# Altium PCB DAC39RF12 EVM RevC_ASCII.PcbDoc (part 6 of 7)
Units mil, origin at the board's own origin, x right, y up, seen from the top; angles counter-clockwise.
Board outline 5071.81 x 2716.54 mil, 16 copper layers (Top Layer, L2 GND1, L3 PWR1, L4 GND2, L5 PWR2, L6 GND3, L7 Ctrl Signal 1, L8 GND4, L9 GND5, L10 Ctrl Signal 2, L11 GND6, L12 PWR3, L13 GND7, L14 PWR4, L15 GND8, Bottom Layer), stack 82.4 mil thick; 596 components, 375 nets, 3310 pads, 1662 vias.
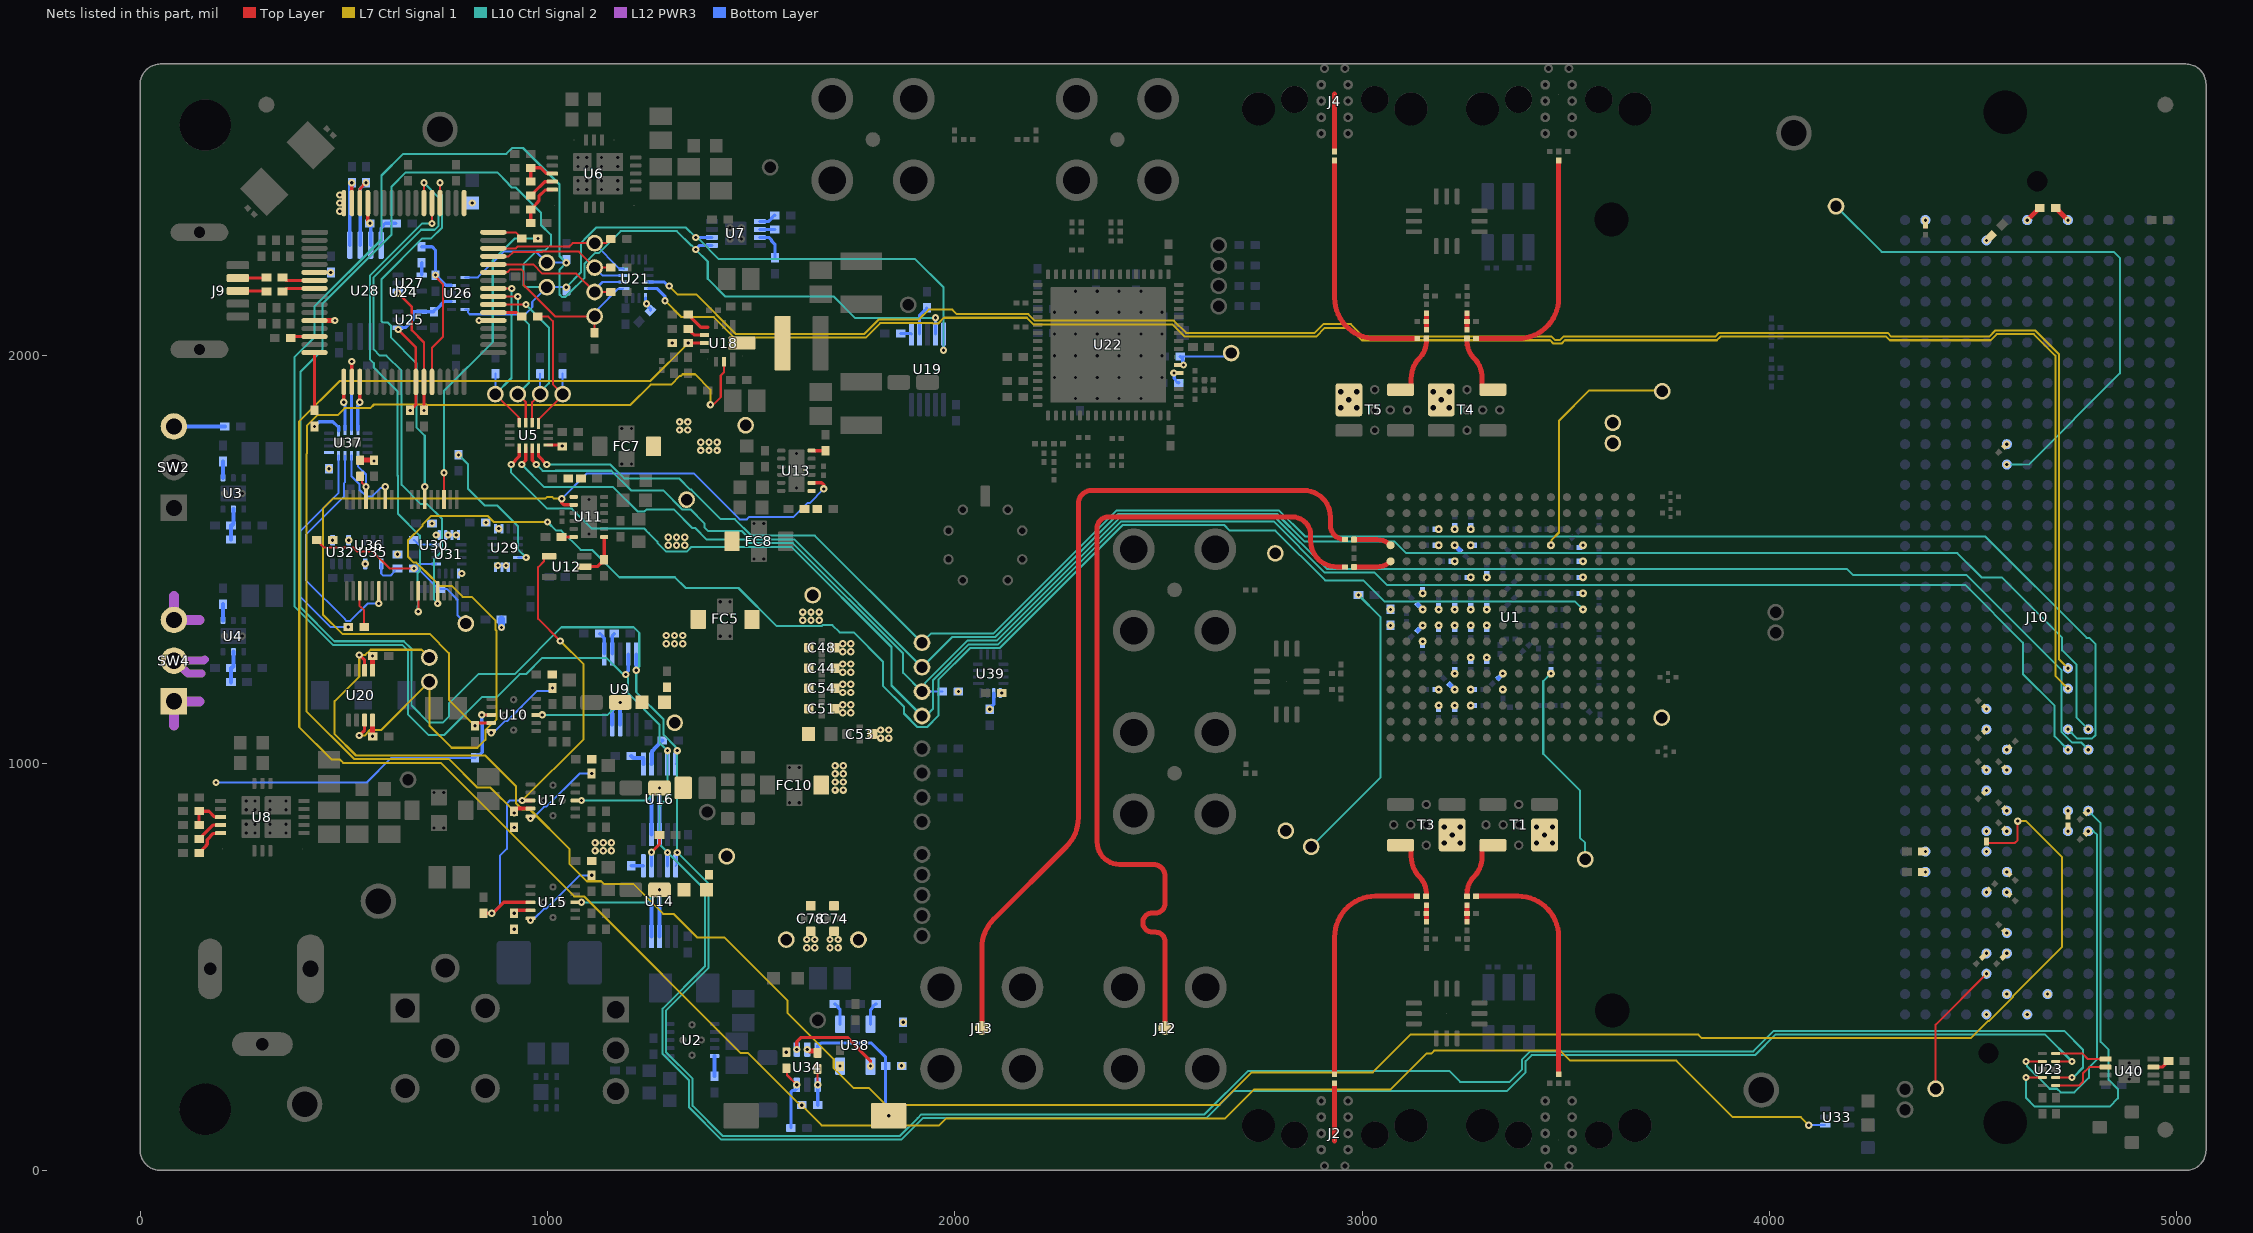
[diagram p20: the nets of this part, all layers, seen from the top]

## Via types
v1: diameter 18, hole 8, Top Layer to Bottom Layer, tented both sides, 1558 vias
v2: diameter 20, hole 10, Top Layer to Bottom Layer, tented both sides, 92 vias
v3: diameter 27, hole 15, Top Layer to Bottom Layer, tented both sides, 12 vias

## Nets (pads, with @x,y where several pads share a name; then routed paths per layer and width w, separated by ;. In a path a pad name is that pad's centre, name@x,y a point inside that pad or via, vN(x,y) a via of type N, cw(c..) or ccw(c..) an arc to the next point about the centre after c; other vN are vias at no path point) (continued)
NetFB3_1: FB3.1 R54.2 U9.8 U9.9 U10.8 | length 336.6
  Top Layer w5: U10.8@972.11,1118.46 v1(987.11,1118.46)
  L10 Ctrl Signal 2 w5: v1(987.11,1118.46) 1147.87,1118.46 v1(1178.58,1149.17)
  Bottom Layer w10: U9.9@1158.89,1094.56 1158.89,1129.49 v1(1178.58,1149.17) U9.8@1178.58,1094.56
NetFB5_1: FB5.1 R71.2 U14.8 U14.9 U15.8 | length 456.6
  Top Layer w5: U15.8@1068.61,658.46 v1(1083.61,658.46)
  L10 Ctrl Signal 2 w5: v1(1083.61,658.46) 1244.33,658.46 v1(1275.08,689.21)
  Bottom Layer w10: U14.9@1255.39,574.59 1255.39,669.52 v1(1275.08,689.21) U14.8@1275.08,574.59
NetFB6_1: FB6.1 R79.2 U16.8 U16.9 U17.8 | length 456.6
  Top Layer w5: U17.8@1068.61,908.46 v1(1083.61,908.46)
  L10 Ctrl Signal 2 w5: v1(1083.61,908.46) 1244.33,908.46 v1(1275.08,939.21)
  Bottom Layer w10: U16.9@1255.39,824.59 1255.39,919.52 v1(1275.08,939.21) U16.8@1275.08,824.59
NetJ2_1: "J2. "@2932.6,75 R10.2 | length 141.4
  Top Layer w12.3: 2932.6,72.62 R10.2@2932.6,214.04
NetJ4_1: "J4. "@2932.6,2641.53 R20.2 | length 141.4
  Top Layer w12.3: R20.2@2932.6,2501.53 2932.6,2642.95
NetJ9_2: J9.2 R124.1 | length 58.5
  Top Layer w8: J9.2@250.16,2190.91 R124.1@308.66,2190.91
NetJ9_3: J9.3 R125.1 | length 58.5
  Top Layer w8: J9.3@250.16,2159.42 R125.1@308.66,2159.42
NetJ10_G12: J10.G12 R156.2
  other v1: 4582.81,1783.06
NetJ10_G13: J10.G13 PP50.1 | length 1402.5
  L10 Ctrl Signal 2 w5: PP50.1@4163.4,2367.25 4275.39,2255.26 4845.07,2255.26 4860,2240.32 4860,1956.94 4636.12,1733.06 v1(4582.81,1733.06)
NetJ10_G27: J10.G27 R161.2
  other v1: 4582.81,1033.06
NetJ10_G28: J10.G28 R163.2
  other v1: 4582.81,983.06
NetJ10_G30: J10.G30 R165.2
  other v1: 4582.81,883.06
NetJ10_G31: J10.G31 R167.2
  other v1: 4582.81,833.06
NetJ10_G33: J10.G33 R169.2
  other v1: 4582.81,733.06
NetJ10_G34: J10.G34 R171.2
  other v1: 4582.81,683.06
NetJ10_G36: J10.G36 R176.2
  other v1: 4582.81,583.06
NetJ10_G37: J10.G37 R177.2 | length 13.3
  Top Layer w8: R177.2@4573.4,523.65 v1(4582.81,533.06)
NetJ10_H25: J10.H25 R158.2
  other v1: 4532.81,1133.06
NetJ10_H26: J10.H26 R159.2
  other v1: 4532.81,1083.06
NetJ10_H28: J10.H28 R160.2
  other v1: 4532.81,983.06
NetJ10_H29: J10.H29 R162.2
  other v1: 4532.81,933.06
NetJ10_H31: J10.H31 R164.2
  other v1: 4532.81,833.06
NetJ10_H32: J10.H32 R166.2
  other v1: 4532.81,783.06
NetJ10_H34: J10.H34 R168.2
  other v1: 4532.83,683.06
NetJ10_H37: J10.H37 R172.2 | length 13.3
  Top Layer w8: R172.2@4523.4,523.65 v1(4532.81,533.06)
NetJ10_H38: J10.H38 PP51.1 | length 334.2
  Top Layer w5: PP51.1@4407.81,200.66 4407.81,358.06 v1(4532.81,483.06)
NetJ10_L1: J10.L1 R178.2 | length 14
  Top Layer w12: R178.2@4382.81,2319.08 v1(4382.81,2333.06)
NetJ10_L32: J10.L32 R179.2
  other v1: 4382.81,783.06
NetJ10_L33: J10.L33 R180.2
  other v1: 4382.81,733.06
NetJ12_1: J12.1 R108.2 | length 2127.1
  Top Layer w12.3: J12.1@2516.35,349.76 2516.35,555.3 2516.35,561.45 ccw(c2492.7,561.45) 2492.7,585.1 2485.07,585.1 cw(c2485.07,608.75) 2485.07,632.4 2492.7,632.4 ccw(c2492.7,656.05) 2516.35,656.05 2516.35,696.3 2516.35,721.78 ccw(c2486.34,721.78) 2486.34,751.79 2404.02,751.79 cw(c2404.02,806.3) 2349.51,806.3 2349.51,1479.83 2349.28,1479.83 2349.28,1576.49 cw(c2377.16,1576.49) 2377.16,1604.37 2828.97,1604.37 cw(c2828.97,1559.51) 2873.83,1559.51 2873.83,1545.65 ccw(c2937.76,1545.65) 2937.76,1481.72 R108.2@2957.76,1481.72
NetJ13_1: J13.1 R110.2 | length 2127.1
  Top Layer w12.3: J13.1@2066.35,349.76 2066.35,546.23 cw(c2166.35,546.23) 2095.64,616.94 2274.13,795.43 ccw(c2203.41,866.14) 2303.41,866.14 2303.41,1637.23 cw(c2335.55,1637.23) 2335.55,1669.36 2857.21,1669.36 cw(c2857.21,1604.42) 2922.16,1604.42 2922.16,1584.42 ccw(c2957.76,1584.42) R110.2@2957.76,1548.82
NetL1_1: L1.1 U18.10
NetPP18_1: PP18.1 R113.2 U22.6 | length 152.4
  Bottom Layer w5: R113.2@2553.54,1998.26 2553.76,1998.26 2660.16,1998.26 2668.72,2006.82 PP18.1@2678.46,2006.82
  Bottom Layer w8: R113.2@2553.76,1998.26 2559.6,1992.42 2559.6,1979.45 v1(2561.51,1977.54)
NetPP32_1: PP32.1 R27.1 R136.1 R141.1 U31.9 | length 537.3
  Top Layer w5: R136.1@433.2,1547.44 435.16,1547.44 442.51,1540.09 442.51,1538.12 451.73,1528.9 485.07,1528.9 485.83,1529.67 523.26,1529.67 533.64,1519.29 571.07,1519.29 612.57,1477.79 v1(672.29,1477.79)
  Bottom Layer w5: PP32.1@800.55,1341.82 PP32.1@799.59,1342.79 778.75,1363.62 778.75,1401.71 752.77,1427.7 736.79,1427.7 R27.1@736.39,1428.1 729.05,1435.44 724.4,1435.44 687.69,1472.15 677.93,1472.15 v1(672.29,1477.79) 673.28,1477.79 679.12,1483.63 679.12,1484.48 683.8,1489.17 U31.9@725.44,1489.17 ; U31.9@725.44,1489.17 U31.9@726.59,1489.17 U31.9@725.44,1489.17
NetPP41_1: PP41.1 R148.2 U1.E6 | length 516.6
  L10 Ctrl Signal 2 w5: v1(3463.51,1219.99) 3444.61,1201.09 3444.61,1023.09 3534.6,933.1 3534.6,817.15 3547.64,804.11 PP41.1@3547.64,762.6
  Bottom Layer w5: v1(3463.51,1219.99) R148.2@3463.51,1228.65
NetPP42_1: PP42.1 U1.N6 | length 599.7
  L7 Ctrl Signal 1 w5: v1(3463.51,1534.95) 3464.43,1535.88 3464.43,1547.36 3483.28,1566.2 3483.28,1840.61 3558.03,1915.36 3734.53,1915.36 cw(c3734.53,1913.06) PP42.1@3736.83,1913.06
NetPP43_1: PP43.1 R149.2 | length 711
  L10 Ctrl Signal 2 w5: PP43.1@2874.85,794.47 3044.81,964.43 3044.81,1359.05 v1(2991.07,1412.79)
NetPP54_1: PP54.1 R138.2 U21.1 U24.43 | length 462.3
  Top Layer w5: U24.43@867.13,2204.69 867.98,2205.54 901.82,2205.54 907.63,2211.35 936.64,2211.35 941.46,2206.53 941.46,2173.86 1018.6,2096.71 PP54.1@1115.72,2096.71 R138.2@1115.72,2056.71
  Bottom Layer w5: PP54.1@1115.72,2096.71 1115.72,2106.45 1125.52,2116.25 1125.52,2116.51 1173.02,2164.02 1184.28,2164.02 U21.1@1185.72,2165.46
NetPP55_1: PP55.1 R139.2 U21.2 U24.44 | length 394.7
  Top Layer w5: U24.44@867.13,2224.38 964.76,2224.38 987.55,2201.58 1070.85,2201.58 PP55.1@1115.72,2156.71 R139.2@1155.72,2156.71
  Bottom Layer w5: PP55.1@1115.72,2161.71 1135.21,2181.2 U21.2@1185.72,2181.2
NetPP56_1: PP56.1 R157.2 U21.3 U24.45 | length 387.6
  Top Layer w5: U24.45@867.13,2244.06 904.9,2244.06 915.58,2254.75 986.72,2254.75 987.55,2255.58 1076.85,2255.58 PP56.1@1115.72,2216.71 R157.2@1155.72,2216.71
  Bottom Layer w5: PP56.1@1115.72,2216.71 1135.48,2196.95 U21.3@1185.72,2196.95
NetPP57_1: PP57.1 R170.2 U21.4 U24.46 | length 397.8
  Top Layer w5: U24.46@867.13,2263.75 922.29,2263.75 926.47,2267.93 1052.82,2267.93 1061.6,2276.71 PP57.1@1115.72,2276.71 1143.75,2276.71 1153.75,2286.71 R170.2@1155.72,2286.71
  Bottom Layer w5: PP57.1@1115.72,2276.71 1115.72,2274.68 1176.26,2214.14 1186.25,2214.14 U21.4@1187.68,2212.7
NetR1_1: R1.1 R3.1 T1.2 | length 159
  Top Layer w12.3: R1.1@3257.61,673.35 3257.61,681.37 cw(c3312.26,681.37) 3273.62,720.02 ccw(c3222.3,771.34) 3294.87,771.34 3294.87,795.39 cw(c3302.6,787.66) 3302.6,798.59 T1.2@3320.99,798.59
NetR1_2: R1.2 R2.2 | length 597.3
  Top Layer w12.3: R1.2@3279.66,673.35 3382.6,673.35 cw(c3382.6,573.35) 3482.6,573.35 3482.6,273.57 R2.2@3482.6,236.09
NetR3_2: R3.2 R4.1 R8.2 | length 40.4
  Top Layer w12.3: R4.1@3257.61,610.9 R8.2@3257.61,631.1 R3.2@3257.61,651.3
NetR5_1: R5.1 R9.1 T3.2 | length 159
  Top Layer w12.3: T3.2@3094.22,798.59 3112.61,798.59 cw(c3112.61,787.66) 3120.33,795.39 3120.33,771.34 ccw(c3192.91,771.34) 3141.59,720.02 cw(c3102.94,681.37) 3157.6,681.37 R5.1@3157.6,673.35
NetR5_2: R5.2 R6.1 R7.2 | length 40.4
  Top Layer w12.3: R6.1@3157.6,610.9 R7.2@3157.6,631.1 R5.2@3157.6,651.3
NetR9_2: R9.2 R10.1 | length 596.5
  Top Layer w12.3: R10.1@2932.6,236.09 2932.6,573.35 cw(c3032.6,573.35) 3032.6,673.35 R9.2@3134.76,673.35
NetR11_1: R11.1 R13.1 T4.2 | length 159
  Top Layer w12.3: R11.1@3257.61,2042.22 3257.61,2034.2 ccw(c3312.27,2034.2) 3273.62,1995.56 cw(c3222.3,1944.24) 3294.87,1944.24 3294.87,1920.19 ccw(c3302.6,1927.91) 3302.6,1916.99 T4.2@3320.99,1916.99
NetR11_2: R11.2 R12.2 | length 597.3
  Top Layer w12.3: R11.2@3279.66,2042.22 3382.6,2042.22 ccw(c3382.6,2142.22) 3482.6,2142.22 3482.6,2442.01 R12.2@3482.6,2479.49
NetR13_2: R13.2 R14.1 R18.2 | length 40.4
  Top Layer w12.3: R13.2@3257.61,2064.27 R18.2@3257.61,2084.47 R14.1@3257.61,2104.67
NetR15_1: R15.1 R19.1 T5.2 | length 159
  Top Layer w12.3: T5.2@3094.22,1916.99 3112.61,1916.99 ccw(c3112.61,1927.91) 3120.33,1920.19 3120.33,1944.24 cw(c3192.91,1944.24) 3141.59,1995.56 ccw(c3102.94,2034.2) 3157.6,2034.2 R15.1@3157.6,2042.22
NetR15_2: R15.2 R16.1 R17.2 | length 40.4
  Top Layer w12.3: R15.2@3157.6,2064.27 R17.2@3157.6,2084.47 R16.1@3157.6,2104.67
NetR19_2: R19.2 R20.1 | length 597.3
  Top Layer w12.3: R20.1@2932.73,2479.49 2932.73,2442.01 2932.73,2142.22 ccw(c3032.73,2142.22) 3032.73,2042.22 R19.2@3135.68,2042.22
NetR22_2: R22.2 U2.10 | length 50
  Bottom Layer w9: R22.2@1410.24,230.95 U2.10@1410.24,280.95
NetR28_1: R28.1 U3.4 | length 40
  Bottom Layer w10: U3.4@203.38,1700.42 R28.1@203.38,1740.42
NetR29_1: R29.1 R32.2 U3.2 | length 78.4
  Bottom Layer w10: R29.1@223.06,1548.65 R32.2@223.06,1583.65 ccw(c223.06,1589.56) 228.97,1589.56 U3.2@228.97,1623.65
NetR30_1: R30.1 U4.4 | length 40
  Bottom Layer w10: U4.4@203.38,1350.42 R30.1@203.38,1390.42
NetR31_1: R31.1 R33.2 U4.2 | length 78.4
  Bottom Layer w10: R31.1@223.06,1198.65 R33.2@223.06,1233.65 ccw(c223.06,1239.56) 228.97,1239.56 U4.2@228.97,1273.65
NetR36_1: R36.1 R40.2 U6.24 | length 115.2
  Top Layer w8: R40.2@959.13,2325.63 R36.1@959.13,2359.63 961.09,2359.63 966.94,2365.47 966.94,2367.44 976.59,2377.1 976.59,2378.13 978.94,2380.47 978.94,2391.79 994.26,2407.11 1011.1,2407.11 U6.24@1011.94,2407.95
NetR39_1: R39.1 R42.2 U6.22 | length 92.7
  Top Layer w8: R42.2@959.13,2427.63 R39.1@959.13,2461.63 983.45,2461.63 996.83,2448.24 1011.02,2448.24 U6.22@1011.94,2447.32
NetR41_2: R41.2 U6.23 | length 68.1
  Top Layer w8: R41.2@959.13,2393.63 961.09,2393.63 966.94,2399.47 966.94,2401.44 993.13,2427.64 U6.23@1011.94,2427.64
NetR44_1: R44.1 U24.38 | length 74.1
  Top Layer w8: U24.38@867.13,2106.27 925.16,2106.27 935.16,2096.27 R44.1@937.13,2096.27
NetR45_1: R45.1 U7.3 | length 100.2
  Bottom Layer w8: R45.1@1558.34,2240.58 1558.34,2273.61 1550.53,2281.42 1550.53,2283.39 1543.34,2290.58 ; 1543.34,2290.58 U7.3@1521.34,2290.58 1543.34,2290.58
NetR47_1: R47.1 U8.24 | length 81.2
  Top Layer w8: R47.1@144.77,779.98 146.74,779.98 152.58,785.83 152.58,787.79 162.24,797.45 162.24,798.48 164.58,800.83 164.58,812.14 179.91,827.47 196.74,827.47 U8.24@197.58,828.31
NetR48_1: R48.1 R50.2 U8.22 | length 92.7
  Top Layer w8: R50.2@144.77,847.98 R48.1@144.77,881.98 169.09,881.98 182.48,868.6 196.66,868.6 U8.22@197.58,867.68
NetR49_2: R49.2 U8.23 | length 68.1
  Top Layer w8: R49.2@144.77,813.98 146.74,813.98 152.58,819.83 152.58,821.79 178.78,847.99 U8.23@197.58,847.99
NetR51_2: R51.2 U9.2 | length 52.2
  Bottom Layer w8: U9.2@1158.89,1267.79 1158.89,1312.4 R51.2@1164.28,1317.79
NetR52_2: R52.2 U9.1 | length 55.7
  Bottom Layer w8: R52.2@1128.3,1317.79 1130.27,1317.79 1136.11,1311.94 1136.11,1309.98 1139.21,1306.88 U9.1@1139.21,1267.79
NetR55_1: R55.1 R57.2 U10.5 | length 195.9
  Bottom Layer w5: v1(861.87,1074.37) 865.39,1074.37 869.61,1078.59 870.99,1078.59 895.43,1103.03 900.74,1103.03 975.24,1177.52 1002.68,1177.52 1009.76,1184.61 v1(1012.11,1184.61)
NetR58_1: R58.1 U11.1 U12.2 | length 112.7
  Top Layer w8: U12.2@1090.56,1482.6 1122.15,1482.6 1131.53,1491.98 1133.5,1491.98 1139.34,1497.82 R58.1@1139.34,1499.79 U11.1@1139.34,1555.42
NetR59_1: R59.1 R61.2 U11.7
NetR60_2: R60.2 U11.12 | length 30
  Top Layer w8: R60.2@1034.54,1555.42 U11.12@1064.54,1555.42
NetR62_1: R62.1 U27.4 | length 30
  Bottom Layer w8: U27.4@691.13,2198.25 R62.1@691.13,2228.25
NetR63_2: R63.2 U7.1 | length 66.4
  Bottom Layer w8: R63.2@1558.34,2344.95 1556.37,2344.95 1550.53,2339.11 1550.53,2337.14 1543.34,2329.95 ; 1543.34,2329.95 U7.1@1521.34,2329.95 1543.34,2329.95
NetR64_1: R64.1 R66.2 U13.7
NetR65_2: R65.2 U13.12 | length 34
  Top Layer w8: U13.12@1648.76,1767.02 R65.2@1682.76,1767.02
NetR67_2: R67.2 U14.2 | length 84.4
  Top Layer w8: v1@1255.47,781.29 v1(1255.39,781.37) 1275.08,801.05 R67.2@1275.08,823.96
  Bottom Layer w8: U14.2@1255.39,747.82 v1(1255.39,781.37)
NetR68_2: R68.2 U14.1 | length 30
  Bottom Layer w8: R68.2@1205.71,747.82 U14.1@1235.71,747.82
NetR72_1: R72.1 R74.2 U15.5 | length 195.9
  Bottom Layer w5: v1(958.37,614.37) 961.89,614.37 966.11,618.59 967.49,618.59 991.93,643.03 997.24,643.03 1078.82,724.61 v1(1108.61,724.61)
NetR75_2: R75.2 U16.2 | length 69.5
  Bottom Layer w10: U16.2@1255.39,997.82 1256.3,998.73 1256.3,1029.16 1266.79,1039.65 1266.79,1040.03 1275.14,1048.38 1275.14,1050.35 1279.98,1055.19 R75.2@1281.95,1055.19
NetR76_2: R76.2 U16.1 | length 46.6
  Bottom Layer w10: R76.2@1205.71,1017.82 1210.55,1012.98 1220.55,1012.98 1220.66,1012.87 1234.8,1012.87 1235.71,1011.97 U16.1@1235.71,997.82
NetR78_2: R78.2 U7.2 | length 37
  Bottom Layer w8: U7.2@1521.34,2310.27 R78.2@1558.34,2310.27
NetR80_1: R80.1 R82.2 U17.5 | length 195.9
  Bottom Layer w5: v1(958.37,864.37) 961.89,864.37 966.11,868.59 967.49,868.59 991.93,893.03 997.24,893.03 1078.82,974.61 v1(1108.61,974.61)
NetR85_2: R85.2 U19.2 | length 72.7
  Bottom Layer w8: U19.2@1913.39,2053.41 1913.39,2099.79 1923.39,2109.8 1925.36,2109.8 1931.2,2115.64 R85.2@1931.2,2117.61
NetR86_2: R86.2 U19.1 | length 27
  Bottom Layer w8: R86.2@1867.19,2054.58 1892.53,2054.58 U19.1@1893.7,2053.41
NetR88_2: R88.2 U18.2 | length 47.5
  Top Layer w8: R88.2@1345.62,2066.18 1347.59,2066.18 1353.43,2060.34 1353.43,2058.37 1360.94,2050.86 U18.2@1385.62,2050.86
NetR89_2: "U18. "@1393.49,2070.05 R89.2 | length 61.9
  Top Layer w8: R89.2@1345.62,2101.18 1347.59,2101.18 1353.43,2095.34 1353.43,2093.37 1376.75,2070.05 1393.49,2070.05
NetR107_1: R107.1 R108.1 U1.M16 | length 93.7
  Top Layer w12.1: R108.1@2979.81,1481.72 3036.34,1481.72 ccw(c3036.34,1529.05) U1.M16@3069.81,1495.58
NetR109_1: R109.1 R110.1 U1.N16 | length 93.7
  Top Layer w12.1: R109.1@2979.81,1548.82 3036.34,1548.82 cw(c3036.34,1501.49) U1.N16@3069.81,1534.95
NetR112_2: R112.2 U22.5 | length 30.3
  Bottom Layer w8: v1(2537.89,1957.85) 2538.48,1957.26 2538.48,1944.74 2541.83,1941.39 2541.83,1939.42 2547.68,1933.57 R112.2@2549.64,1933.57
NetR114_1: R114.1 U24.16 | length 141.9
  Top Layer w8: R114.1@428.16,1865.99 U24.16@428.16,2007.84
NetR117_1: R117.1 U24.48 | length 77.4
  Top Layer w5: U24.48@867.13,2303.12 922.13,2303.12 927.82,2297.43 927.82,2295.46 935.16,2288.12 R117.1@937.13,2288.12
NetR123_1: R123.1 U24.14 | length 60.1
  Top Layer w5: R123.1@369.53,2043.55 R123.1@373.19,2047.21
  Top Layer w8: R123.1@373.19,2047.21 U24.14@428.16,2047.21
NetR124_2: R124.2 U24.7 | length 81.7
  Top Layer w8: R124.2@349.53,2192.41 351.5,2192.41 358.9,2185.01 U24.7@428.16,2185.01
NetR125_2: R125.2 U24.8 | length 81.7
  Top Layer w8: R125.2@349.53,2157.92 351.5,2157.92 358.9,2165.32 U24.8@428.16,2165.32
NetR126_2: R126.2 U24.6 | length 40
  Top Layer w8: U24.6@428.16,2204.69 v1(468.16,2204.69)
NetR127_1: R127.1 U24.62 U28.2 | length 216.5
  Top Layer w8: U24.62@539.38,2374.97 539.83,2375.42 539.83,2410.42 v1(554.38,2424.97)
  Bottom Layer w8: U28.2@540.36,2271.62 540.36,2410.95 546.57,2417.16 548.53,2417.16 554.38,2423 v1(554.38,2424.97)
NetR128_1: R128.1 R130.1 U28.4 | length 84.6
  Bottom Layer w8: U28.4@591.54,2271.62 591.54,2313.27 595.63,2317.36 595.63,2319.33 601.47,2325.17 R130.1@603.44,2325.17 R128.1@628.44,2325.17
NetR129_1: R129.1 U24.63 U28.1 | length 205.4
  Top Layer w8: U24.63@519.69,2374.97 v1(519.69,2424.97)
  Bottom Layer w8: U28.1@514.77,2271.62 514.77,2420.05 v1(519.69,2424.97)
NetR130_2: R130.2 U24.61 U28.3 | length 106.2
  Top Layer w8: U24.61@559.06,2374.97 559.06,2332.89 564.07,2327.88 v1(564.07,2325.17)
  Bottom Layer w8: v1(564.07,2325.17) 565.95,2323.29 U28.3@565.95,2271.62
NetR133_1: R133.1 SW2.2 | length 125
  Bottom Layer w10: SW2.2@82.96,1826.62 R133.1@207.96,1826.62
NetR134_1: R134.1 U29.12 | length 358.8
  L10 Ctrl Signal 2 w5: v1(781.78,1756.81) 804.96,1733.63 804.96,1673.46 845.98,1632.44 877.09,1632.44 927.32,1582.2 927.32,1525.16 v1(947.57,1504.92)
  Bottom Layer w5: U29.12@927.57,1504.92 v1(947.57,1504.92)
NetR136_2: R136.2 U32.4
  other v1: 472.57,1547.44
NetR137_1: R137.1 U31.12 | length 60.5
  Bottom Layer w5: R137.1@671.31,1547.79 673.28,1547.79 679.12,1541.95 679.12,1541.1 683.8,1536.41 U31.12@726.59,1536.41
NetR141_2: R141.2 U35.4 | length 74.3
  Bottom Layer w5: U35.4@591.94,1489.17 591.94,1465.11 596.62,1460.42 614.57,1460.42 624.13,1469.98 624.13,1471.95 629.97,1477.79 R141.2@631.94,1477.79
NetR142_1: R142.1 U37.12 | length 535.9
  Bottom Layer w5: U37.12@487.33,1754.92 487.33,1663.52 390.67,1566.86 390.67,1411.07 467.69,1334.04 v1(510.74,1334.04)
NetR144_2: R144.2 SW3.1 U34.6 | length 340.3
  Bottom Layer w8: U34.6@1663.37,296.94 1663.37,306.78 1667.25,310.65 1669.65,310.65 1671.93,312.93 1795.1,312.93 1830.04,278 R144.2@1830.04,256.93 1830.04,144.05 1837.61,136.47 v1(1837.61,134.36)
NetR145_2: R145.2 U38.1 | length 56.9
  Bottom Layer w8: R145.2@1704.55,408.61 1706.52,408.61 1712.36,402.77 1712.36,400.8 1718.33,394.83 U38.1@1718.33,358.61
NetR146_1: R146.1 R193.2 U34.1 | length 88.8
  Top Layer w5: v1(1663.37,210.32) R193.2@1663.37,249.16
  Bottom Layer w8: R146.1@1663.37,160.32 v1(1663.37,210.32)
NetR147_2: R147.2 U38.3 | length 56.9
  Bottom Layer w8: U38.3@1793.13,358.61 1793.13,394.83 1799.1,400.8 1799.1,402.77 1804.95,408.61 R147.2@1806.91,408.61
NetR150_1: R150.1 U1.H16
  other v1: 3069.81,1338.1
NetR150_2: R150.2 U1.J16
  other v1: 3069.81,1377.47
NetR175_2: R175.2 U40.3 | length 45.2
  Top Layer w8: U40.3@4942.49,253.88 4964.49,253.88 4971.68,261.07 4971.68,263.04 R175.2@4979.49,270.85
NetR192_2: R192.2 R194.1 U34.3 | length 166.9
  Top Layer w5: R192.2@1586.35,250.85 1588.05,249.16 1588.05,234.47 v1(1612.19,210.32)
  Bottom Layer w8: R194.1@1597.66,104.19 1597.66,191.92 1602.35,196.61 1608.32,196.61 1612.19,200.48 v1(1612.19,210.32)
NetU34_4: U34.4 U38.4 | length 241.1
  Top Layer w8: v1(1612.19,296.94) 1612.19,315.72 1623.11,326.63 1735.82,326.63 1792.82,269.64 1792.82,256.57 v1(1793.13,256.25)
PG-C2M: J10.D1 R151.2 | length 43.7
  Top Layer w12: R151.2@4702.5,2363.06 4704.46,2363.06 4708.31,2359.21 4708.31,2357.56 v1(4732.81,2333.06)
PG-M2C: J10.F1 R151.1 | length 43.7
  Top Layer w12: v1(4632.81,2333.06) 4657.31,2357.56 4657.31,2359.21 4661.16,2363.06 R151.1@4663.13,2363.06
PG_VDDL: R69.1 U15.4 | length 43.7
  Top Layer w8: v1(918.37,631.69) 918.37,632.94 924.21,638.78 U15.4@958.37,638.78
PROG_B_SHIFT: J10.D23 U21.11 | length 4409.1
  L7 Ctrl Signal 1 w5: v1(1298.71,2171.2) 1318.96,2150.96 1365.33,2150.96 1462.7,2053.58 1777.47,2053.58 1813.1,2089.22 1911.78,2089.22 1935.76,2113.2 1994.07,2113.2 2004.83,2102.44 2180.38,2102.44 2196.46,2086.37 2537.78,2086.37 2567.87,2056.28 2883.53,2056.28 2905.01,2077.76 2972.53,2077.76 3003.07,2047.22 3465.41,2047.22 3473.31,2039.32 3486.15,2039.32 3494.05,2047.22 3867.16,2047.22 3876.16,2056.22 4290.2,2056.22 4299.2,2047.22 4539.08,2047.22 4554.04,2062.18 4652.54,2062.18 4710.75,2003.97 4710.75,1255.11 v1(4732.81,1233.06)
  Bottom Layer w8: U21.11@1248.71,2181.2 1286.74,2181.2 1296.74,2171.2 v1(1298.71,2171.2)
PRSNT-M2C-L: J10.H2 R155.2 | length 15.6
  Top Layer w12: v1(4532.81,2283.06) R155.2@4543.86,2294.11
PwrGd_DAC_1p0V: R77.1 U17.4 U18.7 | length 2580.5
  Top Layer w5: v1(1400.04,1880.18) 1406.87,1880.18 1425.44,1898.76 1425.44,1951.78 1433.36,1959.7 U18.7@1433.36,1985.41
  Top Layer w10: v1(918.37,877.69) R77.1@918.37,881.69 918.37,883.66 923.21,888.5 929.18,888.5 929.46,888.78 U17.4@958.37,888.78
  L7 Ctrl Signal 1 w5: v1@918.37,881.69 860.1,939.96 828.22,939.96 758.47,1009.72 526.35,1009.72 408.16,1127.91 408.16,1758.82 409.18,1759.84 409.18,1828.15 435.21,1854.18 485.08,1854.18 502.39,1871.49 565.07,1871.49 574.07,1880.49 702.86,1880.49 703.72,1879.63 1203.96,1879.63 1253.51,1929.19 1303.51,1929.19 1325.23,1950.92 1327.88,1950.92 1331.71,1954.74 1362.37,1954.74 1400.04,1917.07 v1(1400.04,1880.18)
PwrGd_DAC_1p8V: R53.1 U10.4 U11.8 U13.8 | length 2277.7
  Top Layer w5: v1(1034.93,1649.16) 1034.93,1639.16 1035.32,1639.16
  Top Layer w8: R53.1@827.71,1098.78 U10.4@861.87,1098.78 ; 1035.32,1639.16 1040.32,1634.16 U11.8@1064.54,1634.16 ; U13.8@1648.76,1688.28 1672.97,1688.28 1677.97,1683.28 1677.97,1673.67 v1(1678.37,1673.28)
  L7 Ctrl Signal 1 w5: v1(821.87,1091.69) 758.08,1155.48 758.08,1269.87 710.69,1317.27 496.44,1317.27 448.71,1365 448.71,1624.9 472.97,1649.16 994.9,1649.16 999.4,1653.66 1011.41,1653.66 1015.91,1649.16 v1(1034.93,1649.16)
  Bottom Layer w5: v1(1034.93,1649.16) 1097.17,1711.41 1358.77,1711.41 1471.86,1598.31 1489.42,1598.31 1495.74,1604.63 1604.34,1604.63 1638.19,1638.48 1643.57,1638.48 v1(1678.37,1673.28)
PwrGd_DAC_Dig: R83.1 R146.2 U18.3 U33.1 | length 6127.8
  Top Layer w8: v1(1345.62,2031.18) U18.3@1385.62,2031.18
  L7 Ctrl Signal 1 w5: v1(1345.62,2031.18) 1252.63,1938.19 489.85,1938.19 390.67,1839.01 390.67,1088.32 470.07,1008.92 490.07,1008.92 498.28,1000.72 737.66,1000.72 1065.41,672.96 1089.61,672.96 1473.63,288.95 1491.66,288.95 1615.47,165.13 1615.68,165.13 1620.49,160.32 v1(1624,160.32) 1673.31,111.02 1961.78,111.02 1978.26,127.5 2663.1,127.5 2734.18,198.58 3069.3,198.58 3157.6,286.88 3169.65,286.88 3177.01,294.23 3486.82,294.23 3511.39,269.66 3771.34,269.66 3910,131 4077.05,131 v1(4096.74,111.32)
  Bottom Layer w5: v1(4096.74,111.32) U33.1@4136.74,111.32
PwrGd_DAC_N1p8V: R70.1 U12.4 U15.3 U17.3 | length 1195.2
  Top Layer w5: U12.4@1003.95,1508.19 996.88,1508.19 991.5,1502.82 991.5,1495.75 977.06,1481.3 977.06,1354.26 v1(1031.51,1299.81)
  Top Layer w8: R70.1@843.53,631.69 v1(863.53,631.69) 866,631.69 892.78,658.46 U15.3@958.37,658.46
  Top Layer w9: v1(938.37,908.46) U17.3@958.37,908.46
  L7 Ctrl Signal 1 w5: v1(938.37,908.46) 1088.93,1059.03 1088.93,1242.38 v1(1031.51,1299.81)
  Bottom Layer w5: v1(863.53,631.69) 883.37,651.53 883.37,772.69 900.11,789.43 900.11,900.52 908.05,908.46 v1(938.37,908.46)
PwrGd_SMPS_analog: "U8. "@202.01,945.93 R46.1 U10.3 | length 800.8
  Top Layer w8: v1(838.69,1118.46) U10.3@861.87,1118.46
  Bottom Layer w5: v1(186.31,952.56) 555.95,952.56 616.34,1012.95 R46.1@821.87,1012.95
  Bottom Layer w8: R46.1@821.87,1012.95 821.87,1014.92 827.71,1020.76 834,1020.76 839.71,1026.48 839.71,1097.89 838.69,1098.92 v1(838.69,1118.46)
RESET_SHIFT: J10.D24 U21.12 | length 4443.1
  L7 Ctrl Signal 1 w5: v1(1288.71,2135.46) 1329.14,2095.02 1408.54,2095.02 1458.97,2044.58 1781.19,2044.58 1816.83,2080.22 1945.44,2080.22 1946.75,2078.91 1958.76,2078.91 1973.3,2093.44 2176.65,2093.44 2192.73,2077.37 2534.05,2077.37 2564.14,2047.28 2887.26,2047.28 2908.74,2068.76 2968.8,2068.76 2999.34,2038.22 3461.69,2038.22 3469.58,2030.32 3489.88,2030.32 3497.78,2038.22 3870.89,2038.22 3879.89,2047.22 4286.47,2047.22 4295.47,2038.22 4542.81,2038.22 4557.77,2053.18 4648.81,2053.18 4701.75,2000.24 4701.75,1214.11 v1(4732.81,1183.06)
  Bottom Layer w8: U21.12@1248.71,2165.46 1268.71,2165.46 1288.71,2145.46 v1(1288.71,2135.46)
S\Y\N\C\_DAC: PP53.1 U1.J4 U20.7 | length 4685.5
  Top Layer w8: v1(537.94,1068.08) 551.08,1081.23 U20.7@551.08,1105.84
  L7 Ctrl Signal 1 w5: v1(537.94,1068.08) 552.34,1068.08 555.27,1071.01 555.27,1072.26 564.35,1081.34 592.15,1081.34 PP53.1@710.18,1199.36 710.18,1092.48 764.83,1037.82 827.88,1037.82 847.37,1057.32 847.37,1080.38 875.25,1108.26 875.25,1273.43 875.31,1273.49 875.31,1324.62 872.75,1327.18 872.75,1350.08 814.45,1408.38 792.04,1408.38 765.1,1435.33 735.91,1435.33 699.45,1471.78 698.8,1471.78 678.3,1492.29 672.19,1492.29 657.69,1506.78 657.69,1546.98 692.67,1581.96 692.67,1585.02 713.88,1606.22 853.93,1606.22 868.07,1592.08 v1(1000.19,1592.08)
  L10 Ctrl Signal 2 w5: v1(1000.19,1592.08) 1021.35,1570.92 1034.1,1570.92 1081.33,1523.69 1109.3,1523.69 1176.62,1456.38 1312.65,1456.38 1339.02,1430.01 1468.97,1430.01 1562.7,1336.29 1673.03,1336.29 1675.58,1338.84 1699.48,1338.84 1717.43,1320.88 1752.32,1320.88 1823.57,1249.63 1823.57,1190.34 1875.23,1138.68 1875.23,1121.87 1908.3,1088.8 1931.95,1088.8 1959.83,1116.69 1959.83,1204.46 2038.16,1282.79 2110.17,1282.79 2412.09,1584.71 2661.64,1584.71 2675.36,1570.98 2787.07,1570.98 2909.11,1448.94 3002.91,1448.94 3055.19,1396.66 3523.06,1396.66 v1(3542.25,1377.47)
S\Y\N\C\_FMC: PP52.1 R164.1 R166.1 U20.2 | length 5814.4
  Top Layer w5: R164.1@4532.81,803.92 R166.1@4532.81,805.1 ; R164.1@4532.83,803.94 4602.55,803.94 4609.24,810.63 v1(4609.24,857.75)
  Top Layer w8: v1(537.94,1265.64) 550.96,1252.62 550.96,1249.73 551.08,1249.6 U20.2@551.08,1227.88
  L7 Ctrl Signal 1 w5: PP52.1@710.18,1259.36 691.16,1278.38 565.76,1278.38 553.02,1265.64 v1(537.94,1265.64) 537.94,1212.55 477.6,1152.21 477.6,1071.19 530.07,1018.72 846.98,1018.72 922.87,942.83 922.87,902.04 938.7,886.21 957.04,886.21 1053.74,789.51 1053.74,753.19 1096.82,710.11 1131.91,710.11 1138.3,703.71 1210.61,703.71 1284.23,630.09 1309.42,630.09 1367.16,572.36 1434.24,572.36 1588.74,417.86 1588.74,387.68 1702.83,273.59 1702.83,251.25 1751.86,202.22 1789.56,202.22 1842.91,148.86 1860.61,148.86 1872.75,161 2649.2,161 2729.22,241.01 3026.07,241.01 3118.36,333.31 3825.67,333.31 3833.98,325 4494.38,325 4536.94,367.56 4539.23,367.56 4598.31,426.63 4598.31,428.93 4718.31,548.93 4718.31,769.48 4630.04,857.75 v1(4609.24,857.75)
SCL_EEPROM: U23.6 U40.6 | length 153.4
  Top Layer w5: U23.6@4702.69,208.61 4760.55,208.61 4769.69,217.75 4769.69,238.33 4785.24,253.88 U40.6@4825.24,253.88
SCL_I2C: PP19.1 R118.1 U7.6 U9.5 U14.5 U16.5 U19.5 U23.7 U26.10 | length 9747.9
  Top Layer w5: U23.7@4702.69,228.29 v1(4742.69,228.29)
  L10 Ctrl Signal 2 w5: PP19.1@998.74,2168.58 946.73,2168.58 941.73,2173.58 941.73,2225.54 975.27,2259.08 994.72,2259.08 1008.17,2272.53 1008.17,2297.21 984.24,2321.15 984.24,2350.78 921.88,2413.13 912.34,2413.13 904.26,2421.21 904.26,2422.62 876.29,2450.59 652.53,2450.59 617.53,2415.59 617.53,2297.93 447.66,2128.06 447.66,2015.01 394.14,1961.49 394.14,1382.14 477.01,1299.27 647.54,1299.27 666.49,1280.32 666.49,1141.47 708.71,1099.25 742.77,1099.25 758.75,1115.23 758.75,1147.07 830.37,1218.69 919.28,1218.69 1034.27,1333.68 1211.45,1333.68 1225.36,1319.76 1225.36,1237.22 1217.95,1229.8 v1(1217.95,1227.79) 1217.95,1174.41 1285.22,1107.13 1285.22,1069.36 1314.44,1040.15 1314.44,1038.35 1318.45,1034.34 v1(1318.45,1030.82) v1(1318.45,780.82) 1395.69,703.58 1395.69,497.44 1365.69,467.44 1291.56,393.31 1291.56,289.75 1356.45,224.86 1356.45,158.51 1430.34,84.62 1864.82,84.62 1908.82,128.62 1917.82,137.62 2613.06,137.62 2720.08,244.64 3213.59,244.64 3240.83,217.4 3362.16,217.4 3392.33,247.57 3392.33,271.99 3412.67,292.33 3960.66,292.33 4010.96,342.64 4723.4,342.64 4769.81,296.22 4769.81,252.8 4745.31,228.29 v1(4742.69,228.29) ; v1(1046.13,2168.58) 1082.09,2204.54 1082.09,2276.71 1091.22,2285.84 1091.22,2286.86 1119.35,2315 1339.67,2315 v1(1364.09,2290.58) 1367.61,2290.58 1372.44,2285.74 1372.58,2285.74 1420.96,2237.36 1902.78,2237.36 1972.44,2167.71 v1(1972.44,2013.41)
  Bottom Layer w5: U26.10@797.38,2113.88 803.2,2113.88 804.64,2112.45 804.64,2106.63 809.18,2102.08 945.18,2102.08 962.63,2119.53 962.63,2132.48 PP19.1@998.74,2168.58 v1(1046.13,2168.58) ; U14.5@1314.45,747.82 1316.45,749.82 1316.45,778.82 v1(1318.45,780.82) ; U16.5@1314.45,997.82 1316.45,999.82 1316.45,1028.82 v1(1318.45,1030.82)
  Bottom Layer w8: v1(1217.95,1227.79) U9.5@1217.95,1267.79 ; v1(1364.09,2290.58) U7.6@1404.09,2290.58 ; v1(1972.44,2013.41) U19.5@1972.44,2053.41
SCL_LOCAL: J10.C30 R152.2 U23.4 | length 1068.6
  Top Layer w5: v1(4629.81,228.29) U23.4@4669.81,228.29
  L10 Ctrl Signal 2 w5: v1(4629.81,228.29) 4629.81,178.42 4651.32,156.91 4835.21,156.91 4855.24,176.94 4855.24,200.01 4832.81,222.45 4832.81,296.22 4813.24,315.79 4813.24,852.63 v1(4782.81,883.06)
SDA_EEPROM: U23.10 U40.5 | length 128.3
  Top Layer w5: U23.10@4702.69,287.35 4768.2,287.35 4781.98,273.57 U40.5@4825.24,273.57
SDA_I2C: PP20.1 R119.1 U7.5 U9.4 U14.4 U16.4 U19.4 U23.9 U26.6 | length 9528.5
  Top Layer w5: U23.9@4702.69,267.66 v1(4742.69,267.66)
  L10 Ctrl Signal 2 w5: v1(1952.76,2093.41) 1754.86,2093.41 1702.63,2145.64 1436.81,2145.64 1393.54,2188.91 1393.54,2231.45 v1(1364.09,2260.9) 1353.76,2271.22 1352.35,2271.22 1317.58,2306 1179.65,2306 1125.86,2252.21 1116.57,2252.21 1091.09,2226.73 1091.09,2191.62 1052.55,2153.08 1044.25,2144.78 1035.32,2144.78 1029.67,2150.44 1029.67,2211.58 v1(1046.4,2228.32) 1029.67,2245.05 1029.67,2420.51 940.04,2510.13 913.75,2510.13 899.29,2495.67 645.51,2495.67 592.53,2442.68 592.53,2285.66 428.16,2121.29 428.16,2045.9 378.64,1996.38 378.64,1384.91 473.29,1290.27 643.75,1290.27 657.49,1276.52 657.49,1119.75 708.33,1068.91 745.95,1068.91 838.98,1161.93 875.25,1161.93 932.01,1218.69 947.4,1218.69 987.13,1258.43 1144.81,1258.43 1182.96,1220.27 1189.87,1220.27 v1(1192.36,1217.79) 1192.36,1214.27 1198.26,1208.36 1198.26,1171.37 1275.08,1094.56 1275.08,1050.51 v1(1294.76,1030.82) 1294.76,914.01 1275.08,894.33 1275.08,800.51 v1(1294.76,780.82) 1386.69,688.89 1386.69,501.17 1282.56,397.04 1282.56,286.02 1347.45,221.13 1347.45,154.78 1426.61,75.62 1868.54,75.62 1921.54,128.62 2616.82,128.62 2683.17,194.96 3355.38,194.96 3401.33,240.91 3401.33,268.26 3416.4,283.33 3964.39,283.33 4014.69,333.64 4676.71,333.64 v1(4742.69,267.66)
  Bottom Layer w5: U26.6@797.38,2192.62 828.84,2192.62 892.25,2256.03 971.28,2256.03 PP20.1@998.74,2228.58 1046.13,2228.58 v1(1046.4,2228.32)
  Bottom Layer w8: v1(1192.36,1217.79) 1192.36,1220.49 1198.26,1226.4 U9.4@1198.26,1267.79 ; U14.4@1294.76,747.82 v1(1294.76,780.82) v1@1294.76,781.37 ; U16.4@1294.76,997.82 v1(1294.76,1030.82) v1@1294.76,1031.37 ; v1(1364.09,2260.9) 1374.09,2270.9 U7.5@1404.09,2270.9 ; U19.4@1952.76,2053.41 v1(1952.76,2093.41)
SDA_LOCAL: J10.C31 R154.2 U23.2 | length 875.8
  Top Layer w5: v1(4629.81,267.66) U23.2@4669.81,267.66
  L10 Ctrl Signal 2 w5: v1(4629.81,267.66) 4632.01,265.46 4632.01,256.53 4687.88,200.66 4705.92,200.66 4714.82,191.75 4748.34,191.75 4783.95,227.36 4783.95,252.32 4804.24,272.61 4804.24,824.1 4795.28,833.06 v1(4782.81,833.06)
TDI_FMC: J10.D30 R153.2 | length 14
  Top Layer w8: R153.2@4732.81,869.08 v1(4732.81,883.06)
TDO_FMC: J10.D31 R153.1 | length 14
  Top Layer w8: v1(4732.81,833.06) R153.1@4732.81,847.03
USB_C\S\_DAC_3p3: U24.19 U37.4 | length 120.1
  Top Layer w8: v1(539.38,1885.99) U24.19@539.38,1935.99
  Bottom Layer w8: U37.4@534.57,1817.92 534.57,1878.48 539.38,1883.29 v1(539.38,1885.99)
USB_C\S\_FPGA_1p8: J10.D27 PP33.1 U5.9 | length 4764
  Top Layer w8: v1(910.98,1733.1) 930.98,1753.1 U5.9@930.98,1773.1
  L10 Ctrl Signal 2 w5: v1(910.98,1733.1) 910.98,1713.08 999.4,1624.66 1060.01,1624.66 1108.21,1576.45 1237.01,1576.45 1248.85,1564.62 1269.84,1543.62 1269.84,1541.14 1290.83,1520.15 1342.84,1520.15 1353.67,1530.97 1598.82,1530.97 1844.65,1285.13 1844.65,1190.63 PP33.1@1919.48,1115.8 1929.23,1115.8 1946.48,1133.06 1946.48,1203.84 2034.43,1291.79 2106.44,1291.79 2408.36,1593.71 2782.74,1593.71 2908.6,1467.85 3030.71,1467.85 3060.81,1437.76 4480.17,1437.76 4622.31,1295.61 4622.31,1218.94 4700,1141.25 4700,1065.87 v1(4732.81,1033.06)
USB_C\S\_FPGA_3p3: PP47.1 R111.2 U5.4 U24.41 | length 465.1
  Top Layer w5: U24.41@867.13,2165.32 v1(912.13,2165.32) ; PP47.1@872.24,1906.09 929.54,1848.78 929.54,1837.52 U5.4@930.98,1836.09
  L10 Ctrl Signal 2 w5: PP47.1@872.24,1906.09 911.63,1945.49 911.63,2164.82 v1(912.13,2165.32)
  Bottom Layer w5: PP47.1@872.24,1906.09 R111.2@872.24,1956.09
USB_C\S\_LMK_3p3: U24.54 U30.13 | length 1313.4
  Top Layer w5: U24.54@696.86,2374.97 v1(696.86,2424.97) ; v1(730.28,1392.03) U30.13@730.28,1423.03
  L10 Ctrl Signal 2 w5: v1(696.86,2424.97) 732.04,2389.78 732.04,2318.55 722.96,2309.47 689.79,2309.47 573.06,2192.74 573.06,2016.06 588.63,2000.49 604.44,2000.49 642.03,1962.9 642.03,1683.19 689.18,1636.04 704.7,1636.04 741.09,1599.66 741.09,1520.66 721.64,1501.22 721.64,1401.45 730.28,1392.82 v1(730.28,1392.03)
USB_CS_DAC_1p8: R187.2 U36.13 U37.9 | length 147.7
  Top Layer w5: R187.2@540.28,1704.44 544.81,1699.91 544.81,1688.16 v1(554.53,1678.44) U36.13@554.53,1647.44
  Bottom Layer w5: U37.9@534.57,1754.92 534.57,1728.59 554.53,1708.62 v1(554.53,1678.44)
USB_I2C_SCL: R115.2 R116.2 U24.26 U25.1 U25.4 U26.2 | length 394.3
  Top Layer w6: v1(633.43,2064.44) 677.17,2020.7 U24.26@677.17,1935.99
  Top Layer w8: v1(662.86,1865.99) 662.86,1867.96 668.7,1873.8 670.67,1873.8 677.17,1880.31 U24.26@677.17,1935.99
  Bottom Layer w8: U25.1@632.86,2068.86 633.43,2069.44 651.21,2069.44 671.13,2089.36 671.13,2108.23 U25.4@691.13,2108.23 R116.2@721.13,2108.23 721.13,2110.2 726.97,2116.04 728.94,2116.04 746.46,2133.57 U26.2@764.51,2133.57
USB_I2C_SDAr: R62.2 R122.2 U24.28 U26.4 | length 432.2
  Top Layer w6: U24.28@716.54,1935.99 716.54,2019.69 743.61,2046.76 743.61,2175.76 v1@721.13,2198.25
  Bottom Layer w8: R62.2@691.13,2267.62 716.65,2267.62 725.13,2259.15 v1(725.13,2198.25) 725.13,2196.28 730.97,2190.44 732.94,2190.44 750.44,2172.94 U26.4@764.51,2172.94
USB_I2C_SDAw: R121.2 U24.27 U27.1 | length 314.4
  Top Layer w6: v1(632.86,2153.88) 667.29,2119.45 667.29,2062.68 696.86,2033.11 U24.27@696.86,1935.99
  Top Layer w8: v1(696.86,1865.99) U24.27@696.86,1935.99
USB_SCLK_DAC_1p8: R142.2 U36.3 | length 94.3
  Top Layer w5: U36.3@538.79,1423.03 538.79,1385.65 541.72,1382.72 542.76,1382.72 550.11,1375.38 R142.2@550.11,1334.04
USB_SCLK_DAC_3p3: R114.2 U37.1 | length 79.1
  Bottom Layer w8: v1(428.16,1826.62) 439.97,1838.43 473.02,1838.43 485.73,1825.73 487.26,1825.73 487.33,1825.66 U37.1@487.33,1815.95
USB_SCLK_FPGA_1p8: J10.D26 PP34.1 U5.12 | length 4606.6
  Top Layer w8: U5.12@978.22,1773.1 978.22,1753.1 v1(998.22,1733.1)
  L10 Ctrl Signal 2 w5: v1(998.22,1733.1) 1154.22,1733.1 1188.14,1699.18 1323.02,1699.18 1350.56,1671.64 1353.47,1671.64 1425.84,1599.27 1460.19,1599.27 1500.85,1558.61 1656.67,1558.61 PP34.1@1919.48,1295.8 1942.47,1318.79 2095.26,1318.79 2397.18,1620.71 2795.7,1620.71 2860.05,1556.36 4530.01,1556.36 4778.6,1307.77 4784.77,1307.77 4800.74,1291.81 4800.74,1069.15 4791.71,1060.13 4755.74,1060.13 v1(4732.81,1083.06)
USB_SCLK_FPGA_3p3: PP44.1 R44.2 R132.2 U5.1 | length 376.7
  Top Layer w5: R44.2@976.5,2096.27 1001.95,2096.27 1013.14,2085.08 1013.14,1930.18 PP44.1@1037.24,1906.09 1037.24,1903.12 979.66,1845.54 979.66,1835.56 U5.1@978.22,1834.12
  Bottom Layer w5: PP44.1@1037.24,1906.09 R132.2@1037.24,1956.09
USB_SCLK_LMK_3p3: R117.2 U30.3 | length 769.5
  Top Layer w5: U30.3@746.03,1647.44 v1(746.03,1713.13)
  L10 Ctrl Signal 2 w5: v1(746.03,1713.13) 746.03,1913.77 865.69,2033.43 865.69,2234.18 919.62,2288.12 v1(976.5,2288.12)
USB_SDI_DAC_1p8: U36.6 U37.11 | length 645.8
  Top Layer w5: v1(586.03,1392.03) U36.6@586.03,1423.03
  Top Layer w8: v1(586.03,1392.03) U36.6@586.03,1423.03
  Bottom Layer w5: U37.11@503.08,1754.92 503.08,1689.86 499.95,1686.74 499.95,1653.92 406.99,1560.96 406.99,1449.11 503.08,1353.03 503.08,1352.47 506,1349.54 516.28,1349.54 558.76,1392.03 v1(586.03,1392.03)
USB_SDI_DAC_3p3: U24.17 U37.2 | length 119.3
  Top Layer w8: v1(500.01,1885.99) U24.17@500.01,1935.99
  Bottom Layer w8: v1(500.01,1885.99) 500.01,1883.29 503.08,1880.22 U37.2@503.08,1817.92
USB_SDI_FPGA_1p8: J10.C26 PP30.1 U5.11 | length 4535.1
  Top Layer w8: U5.11@962.48,1773.1 962.48,1743.1 v1(972.48,1733.1)
  L10 Ctrl Signal 2 w5: v1(972.48,1733.1) 987.98,1717.6 1019.75,1717.6 1019.96,1717.81 1156.78,1717.81 1205.09,1669.49 1284.46,1669.49 1331.32,1622.64 1351.6,1622.64 1385.33,1588.9 1385.33,1584.9 1385.33,1578.76 1393.83,1570.27 1476.46,1570.27 1497.12,1549.61 1605.67,1549.61 PP30.1@1919.48,1235.8 1993.47,1309.79 2098.99,1309.79 2400.91,1611.71 2791.1,1611.71 2858.19,1544.61 3079.01,1544.61 3108.26,1515.36 4461.29,1515.36 4520.44,1456.21 4569.87,1456.21 4718.31,1307.77 4718.31,1277.05 4754.05,1241.31 4754.05,1111.81 v1(4782.81,1083.06)
USB_SDI_FPGA_3p3: PP45.1 R131.2 U5.2 U24.39 | length 460.2
  Top Layer w5: U24.39@867.13,2125.95 v1(947.13,2125.95) ; U5.2@962.48,1836.09 962.48,1886.33 PP45.1@982.24,1906.09
  L10 Ctrl Signal 2 w5: v1(947.13,2125.95) 1003.51,2069.57 1003.51,1932.51 982.24,1911.23 PP45.1@982.24,1906.09
  Bottom Layer w5: PP45.1@982.24,1906.09 R131.2@982.24,1956.09
USB_SDI_LMK_3p3: U24.52 U30.6 | length 954.9
  Top Layer w5: U30.6@698.79,1647.44 v1(698.79,1678.44) ; U24.52@736.23,2374.97 v1(736.23,2424.97)
  L10 Ctrl Signal 2 w5: v1(698.79,1678.44) 698.79,1804.19 678.36,1824.62 678.36,1982.16 616.04,2044.48 616.04,2073.22 607.55,2081.71 595.46,2081.71 592.53,2084.64 592.53,2188.03 692.73,2288.23 714.45,2288.23 741.04,2314.82 741.04,2393.51 736.23,2398.33 v1(736.23,2424.97)
USB_SDO_DAC_1p8: U36.10 U37.10 | length 202.5
  Top Layer w5: U36.10@601.78,1647.44 v1(601.78,1678.44)
  Bottom Layer w5: U37.10@518.82,1754.92 518.82,1704.57 538.54,1684.86 538.54,1671.23 554.77,1654.99 570.28,1654.99 591.24,1675.95 599.29,1675.95 v1(601.78,1678.44)
USB_SDO_DAC_3p3: U24.18 U37.3 | length 218.4
  Top Layer w8: U24.18@519.69,1935.99 v1(519.69,1985.99)
  Bottom Layer w8: U37.3@518.82,1817.92 518.82,1985.12 v1(519.69,1985.99)
USB_SDO_FPGA_1p8: J10.C27 PP25.1 R120.2 U5.10 | length 4712.9
  Top Layer w8: v1(936.73,1733.1) 946.73,1743.1 U5.10@946.73,1773.1
  L10 Ctrl Signal 2 w5: v1(936.73,1733.1) 991.39,1678.44 1160.7,1678.44 1221.37,1617.76 1237.87,1617.76 1243.33,1623.23 1310,1623.23 1355.83,1577.39 1362.41,1577.39 1390.2,1549.61 1484.39,1549.61 1493.39,1540.61 1598.82,1540.61 1599.45,1539.97 1602.54,1539.97 1873.33,1269.18 1873.33,1221.95 PP25.1@1919.48,1175.8 1926.37,1182.69 1926.37,1196.45 2030.71,1300.79 2102.71,1300.79 2404.63,1602.71 2787.37,1602.71 2913.23,1476.85 3034.44,1476.85 3034.52,1476.77 4190.11,1476.77 4204.55,1462.33 4482.81,1462.33 4717.31,1227.83 4717.31,1076.26 4742.44,1051.13 4764.74,1051.13 v1(4782.81,1033.06)
  Bottom Layer w5: PP25.1@1919.48,1175.8 R120.2@1969.48,1175.8
USB_SDO_FPGA_3p3: PP46.1 U5.3 U24.40 | length 400.2
  Top Layer w5: U24.40@867.13,2145.64 v1(927.13,2145.64) ; PP46.1@927.24,1906.09 946.73,1886.6 U5.3@946.73,1836.09
  L10 Ctrl Signal 2 w5: v1(927.13,2145.64) 927.13,2104.3 954.39,2077.04 954.39,1933.24 PP46.1@927.24,1906.09
USB_SDO_LMK_3p3: U24.53 U30.10 | length 1185.6
  Top Layer w5: v1(683.04,1372.03) U30.10@683.04,1423.03 ; v1(716.54,2324.97) U24.53@716.54,2374.97
  L10 Ctrl Signal 2 w5: v1(683.04,1372.03) 681.37,1373.7 681.37,1385.6 681.79,1386.02 681.79,1398.03 680.99,1398.83 680.99,1465.98 686.79,1471.78 686.79,1558.26 633.03,1612.02 633.03,1704.86 631.9,1705.99 631.9,1912.9 573.56,1971.23 573.56,1982 564.06,1991.5 564.06,2196.47 692.56,2324.97 v1(716.54,2324.97)
VADJ_FMC: J10.E39 J10.F40 J10.G39 J10.H40 SW4.3 | length 121.5
  L12 PWR3 w25: 82.96,1093.23 SW4.3@82.96,1151.62 146.08,1151.62
  other v1: 4532.81,383.06 4632.81,383.06 4582.81,433.06 4682.81,433.06
VCORE: C39.2 U24.12 U24.37 U24.49 U24.64 | length 84.5
  Top Layer w5: v1(832.13,2086.58) U24.37@866.66,2086.58
  Top Layer w12: U24.12@428.16,2086.58 v1(478.16,2086.58)
  other v1: 490.01,2354.97 490.01,2374.97 815.28,2374.97 490.01,2394.97
VDD_FPGA: C20.2 C70.2 C98.2 C108.2 C162.2 C164.2 R120.1 SW4.1 U5.13 U20.1 U21.13 U29.5 U29.6 U29.14 U29.15 U29.16 U31.5 U31.14 U31.15 U31.16 U39.13 | length 280.3
  Top Layer w8: U5.13@1001.85,1780.97 1033.58,1780.97 v1(1036.09,1778.47)
  Top Layer w12: U20.1@570.77,1227.88 v1(570.77,1262.88)
  L12 PWR3 w20: SW4.1@82.96,1251.62 SW4.1@85.62,1251.62 ; 150.37,1220.08 117.15,1220.08 SW4.1@85.62,1251.62 ; 158.7,1254.23 156.09,1251.62 SW4.1@85.62,1251.62
  Bottom Layer w8: U21.13@1240.83,2141.83 1240.9,2141.77 1240.9,2132.74 1243.34,2130.3 v1(1243.34,2127.59) 1243.34,2124.89 1252.77,2115.46 C70.2@1252.77,2111.21
  Bottom Layer w18: v1(887.25,1333.18) C162.2@887.25,1353.03
  other v1: 2115.5,1172.18 2008.85,1175.8 789.58,1465.55 878.33,1485.29 898.08,1485.29 756.08,1560.03 775.83,1560.03 880.33,1575.78 848.92,1590.72 1324.45,1817.79 1344.45,1817.79 1324.45,1837.79 1344.45,1837.79
VDDA: C44.1 C46.2 C48.1 C51.1 C54.1 FB3.2 FB4.1 FC5.1 PP5.1
VDDA18A: C44.3 C231.2 C232.2 PP6.1 T1.3 T3.3 U1.G14 U1.H14 | length 25.5
  Bottom Layer w5: C231.2@3148.55,1290.07 v1(3148.55,1298.73)
  Bottom Layer w10: C232.2@3136.66,1326.21 v1(3148.55,1338.1)
  other v1: 1724.86,1223.43 1744.86,1223.43 1724.86,1243.43 1744.86,1243.43
VDDA18B: C48.3 C233.2 C234.2 PP7.1 T4.3 T5.3 U1.J14 U1.K14 | length 25.5
  Bottom Layer w5: v1(3148.55,1416.84) C234.2@3148.55,1425.5
  Bottom Layer w10: C233.2@3136.66,1389.36 v1(3148.55,1377.47)
  other v1: 1724.86,1273.43 1744.86,1273.43 1724.86,1293.43 1744.86,1293.43
VDDCLK10: C202.2 C203.2 C204.2 C205.2 C206.2 C207.2 FC10.3 U1.E12 U1.F11 U1.H11 U1.J11 U1.L11 U1.M12 | length 52
  Bottom Layer w5: C207.2@3218.62,1495.58 v1(3227.29,1495.58) ; v1(3227.29,1219.99) C202.2@3227.29,1228.65 ; C206.2@3258,1456.21 v1(3266.66,1456.21) ; C203.2@3266.66,1250.7 v1(3266.66,1259.36) ; C204.2@3266.66,1329.44 v1(3266.66,1338.1) ; v1(3266.66,1377.47) C205.2@3266.66,1386.13
  other v1: 1706.18,933.87 1726.18,933.87 1706.18,953.87 1726.18,953.87 1706.18,973.87 1726.18,973.87 1706.18,993.87 1726.18,993.87
VDDCLK18: C51.3 C208.2 C209.2 PP8.1 U1.H12 U1.H13 | length 17.3
  Bottom Layer w5: C209.2@3187.92,1329.44 v1(3187.92,1338.1) ; C208.2@3227.29,1329.44 v1(3227.29,1338.1)
  other v1: 1724.86,1123.43 1744.86,1123.43 1724.86,1143.43 1744.86,1143.43
VDDIO: C34.2 C84.2 C165.2 C169.2 C171.2 C239.2 C240.2 FC5.3 PP35.1 R69.2 R77.2 R83.2 R140.1 R143.2 R144.1 R186.1 R187.1 R192.1 R193.1 SW4.2 U1.D9 U1.E9 U20.8 U31.13 U32.5 U34.5 U35.5 U37.13 U38.5 U39.14 | length 286.8
  Top Layer w12: R187.1@540.28,1743.81 572.28,1743.81 v1(574.28,1741.81) ; v1(570.77,1065.84) U20.8@570.77,1105.84 ; v1(1637.78,296.94) 1639.41,296.94 1643.31,293.04 1659.53,293.04 1663.37,289.2 R193.1@1663.37,288.53
  L12 PWR3 w25: 82.96,1410.01 SW4.2@82.96,1351.62 146.08,1351.62
  Bottom Layer w8: v1(2085.82,1132.18) 2085.82,1134.15 2095.82,1144.15 U39.14@2095.82,1172.18
  Bottom Layer w10: C240.2@3333.51,1208.1 v1(3345.4,1219.99)
  other v1: 1718.33,256.25 1869.41,256.93 1586.35,290.22 1873.33,363.75 918.37,592.32 1116.95,784.67 1136.95,784.67 1156.95,784.67 1116.95,804.67 1136.95,804.67 1156.95,804.67 918.37,842.32 3345.4,1180.62 1291.92,1293.29 1311.92,1293.29 1331.92,1293.29 1291.92,1313.29 1311.92,1313.29 1331.92,1313.29 1627.02,1350.79 1647.02,1350.79 1667.02,1350.79 1627.02,1370.79 1647.02,1370.79 1667.02,1370.79 552.57,1489.17 631.94,1512.79 511.94,1547.44 726.59,1560.03 716.54,1588.38 463.71,1722.8 1306.25,2031.18
VDDL: C74.1 C76.2 C78.1 FB5.2 PP13.1
VDDLA: C74.3 C225.2 C226.2 PP14.1 U1.F10 U1.H10 | length 17.3
  Bottom Layer w5: C225.2@3306.03,1250.7 v1(3306.03,1259.36) ; C226.2@3306.03,1329.44 v1(3306.03,1338.1)
  other v1: 1693.55,546.92 1713.55,546.92 1693.55,566.92 1713.55,566.92
VDDLB: C78.3 C227.2 C228.2 PP15.1 U1.J10 U1.L10 | length 17.3
  Bottom Layer w5: v1(3306.03,1377.47) C227.2@3306.03,1386.13 ; v1(3306.03,1456.21) C228.2@3306.03,1464.87
  other v1: 1636.35,546.92 1656.35,546.92 1636.35,566.92 1656.35,566.92
VDDR: C54.3 C241.2 C242.2 C243.2 C244.2 PP10.1 U1.K4 U1.L4 U1.M4 U1.N4 | length 34.6
  Bottom Layer w5: C242.2@3533.59,1416.84 v1(3542.25,1416.84) ; C243.2@3533.59,1456.21 v1(3542.25,1456.21) ; C241.2@3533.59,1495.58 v1(3542.25,1495.58) ; C244.2@3533.59,1534.95 v1(3542.25,1534.95)
  other v1: 1724.86,1173.43 1744.86,1173.43 1724.86,1193.43 1744.86,1193.43
VDDSYS18: C53.3 C229.2 C230.2 PP9.1 U1.J12 U1.J13 | length 17.3
  Bottom Layer w5: v1(3187.92,1377.47) C230.2@3187.92,1386.13 ; v1(3227.29,1377.47) C229.2@3227.29,1386.13
  other v1: 1817.86,1061.46 1837.86,1061.46 1817.86,1081.46 1837.86,1081.46
VEExA: C219.1 C220.1 C221.1 C222.1 C223.1 C224.1 FC7.3 PP11.1 U1.C11 U1.C12 U1.C13 U1.D11 U1.D12 U1.D13 | length 60.1
  Bottom Layer w5: C221.1@3179.26,1180.62 v1(3187.92,1180.62) ; C219.1@3187.92,1132.59 v1(3187.92,1141.25) ; C222.1@3227.29,1132.59 v1(3227.29,1141.25) ; v1(3266.66,1141.25) C223.1@3275.32,1141.25 ; v1(3266.66,1180.62) C224.1@3275.32,1180.62
  Bottom Layer w10: C220.1@3215.4,1192.51 v1(3227.29,1180.62)
  other v1: 1376.46,1767.79 1396.46,1767.79 1416.46,1767.79 1376.46,1787.79 1396.46,1787.79 1416.46,1787.79
VEExB: C196.1 C197.1 C198.1 C199.1 C200.1 C201.1 FC8.3 PP12.1 U1.N11 U1.N12 U1.N13 U1.P11 U1.P12 U1.P13 | length 60.1
  Bottom Layer w5: C197.1@3179.26,1534.95 v1(3187.92,1534.95) ; C196.1@3179.26,1574.32 v1(3187.92,1574.32) ; v1(3227.29,1574.32) C201.1@3227.29,1582.98 ; v1(3266.66,1534.95) C199.1@3275.32,1534.95 ; v1(3266.66,1574.32) C200.1@3266.66,1582.98
  Bottom Layer w12: v1(3227.29,1534.95) C198.1@3239.18,1523.06
  other v1: 1296.84,1534.65 1316.84,1534.65 1336.84,1534.65 1296.84,1554.65 1316.84,1554.65 1336.84,1554.65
